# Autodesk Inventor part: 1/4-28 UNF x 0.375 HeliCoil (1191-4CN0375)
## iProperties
Title: 1/4-28 UNF x 0.375 HeliCoil (1191-4CN0375)
Author: CFitzwater
Shininess: 64.0
Angle Display Precision: 2
Document Length Units: 11272
Document Angle Units: 11286
Document Time Units: 11279
Document Mass Units: 11290
Document Length Units Precision: 3
Document Angle Units Precision: 2
Compacted: True
PropertySet Name: _Private Model Information
Created: 2002-02
Part Number: Helicoil-1191-CN
Material: Stainless Steel, Austenitic
Document SubType Name: Modeling
Designer: CFitzwater
Control State: 0
Master: False
Checked Out: False
PropertySet Name: Design Tracking Control
Density: 7.750000000000001
Volumn: 0.37239295650448834
Area: 5.5389113408432396
PropertySet Name: Model Information
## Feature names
1. Extrusion1
2. Chamfer1
3. Chamfer2
